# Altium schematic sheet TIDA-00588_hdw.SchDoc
size 431 x 279 mm; Date: Not shown in title block; ApprovedBy: Not shown in title block; CheckedBy: Not shown in title block; Author: Not shown in title block; CompanyName: Not shown in title block; Engineer: Not shown in title block; Organization: Not shown in title block; Address1: Not shown in title block; Address2: Not shown in title block; Address3: Not shown in title block; Address4: Not shown in title block; DocumentNumber: 1; Revision: Use project parameter SCH_Rev; SheetNumber: 3; SheetTotal: 3; PageSetup: Record=PageOptions¦CenterHorizontal=True¦CenterVertical=True¦PrintScale=1.00¦XCorrection=1.00¦YCorrection=1.00¦PrintKind=0¦BorderSize=5000000¦LeftOffset=0¦BottomOffset=0¦Orientation=2¦PaperLength=1000¦PaperWidth=1000¦Scale=100¦PaperSource=15¦PrintQuality=600¦MediaType=1¦DitherType=10¦PaperKind=Letter¦PrintScaleMode=1
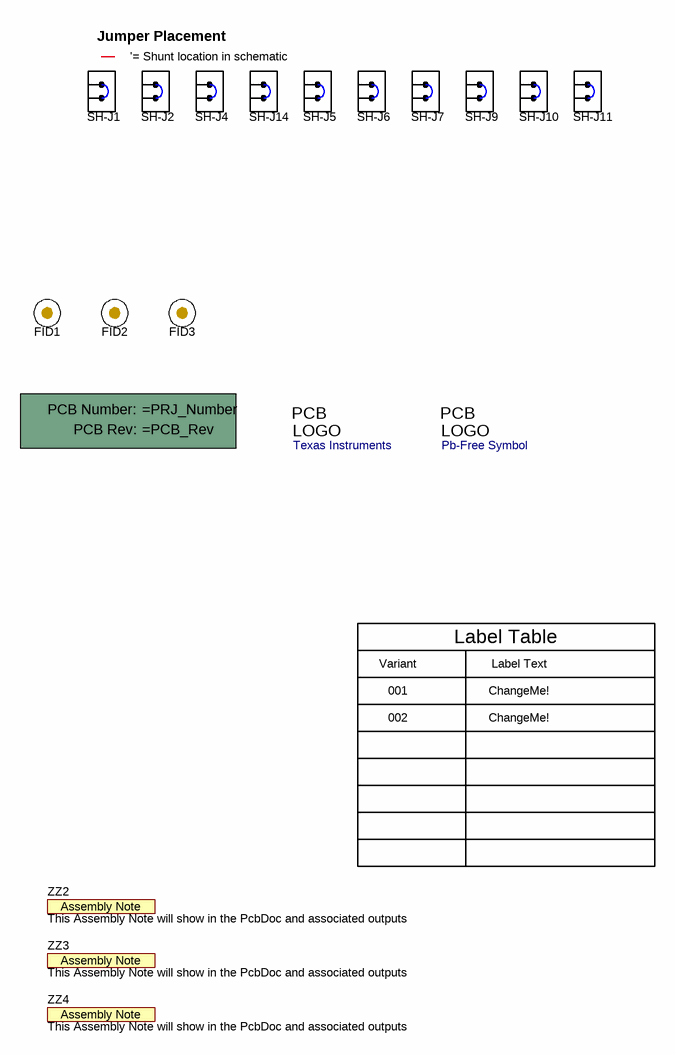
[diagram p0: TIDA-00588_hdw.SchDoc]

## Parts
!PCB1  Printed Circuit Board  (value not drawn)  (mechanical)
FID1  Fiducial  [Fiducial10-20]  (value not drawn)
FID2  Fiducial  [Fiducial10-20]  (value not drawn)
FID3  Fiducial  [Fiducial10-20]  (value not drawn)
Logo1  Texas Instruments  [TI_Stacked_SolderMask_Small]  (no BOM)
Logo2  Pb-Free Symbol  [Pb-Free_Overlay_Small]  (no BOM)
SH-J1  969102-0000-DA  [SNT-100-BK-G]  (value not drawn)
SH-J2  969102-0000-DA  [SNT-100-BK-G]  (value not drawn)
SH-J4  969102-0000-DA  [SNT-100-BK-G]  (value not drawn)
SH-J5  969102-0000-DA  [SNT-100-BK-G]  (value not drawn)
SH-J6  969102-0000-DA  [SNT-100-BK-G]  (value not drawn)
SH-J7  969102-0000-DA  [SNT-100-BK-G]  (value not drawn)
SH-J9  969102-0000-DA  [SNT-100-BK-G]  (value not drawn)
SH-J10  969102-0000-DA  [SNT-100-BK-G]  (value not drawn)
SH-J11  969102-0000-DA  [SNT-100-BK-G]  (value not drawn)
SH-J14  969102-0000-DA  [SNT-100-BK-G]  (value not drawn)
ZZ2  This Assembly Note will show in the PcbDoc and associated outputs  [AssemblyNote]  (no BOM)
ZZ3  This Assembly Note will show in the PcbDoc and associated outputs  [AssemblyNote]  (no BOM)
ZZ4  This Assembly Note will show in the PcbDoc and associated outputs  [AssemblyNote]  (no BOM)

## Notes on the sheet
- Jumper Placement
- '= Shunt location in schematic
- Variant
- Label Table
- Label Text
- 001
- 002
- ChangeMe!

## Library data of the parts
!PCB1 = PCB: Manufacturer: Any; SymbolCreator: a0412235
FID1-FID3 = Fiducial: Fiducial mark.  There is nothing to buy or mount.; SymbolCreator: codlsc
Logo1 = TI_Logo: Texas Instrument Corporate Signature; SymbolCreator: a0412235
Logo2 = Pb-Free: SymbolCreator: a0412235
SH-J1 SH-J2 SH-J4-SH-J7 SH-J9-SH-J11 SH-J14 = 969102-0000-DA: Shunt, 100mil, Gold plated, Black; Manufacturer: 3M; Alternate Manufacturer: Samtec; Value: 1x2; Note: You can "mate" this to a header by matching the designator.  i.e. use SH-J3 for header J3
ZZ2-ZZ4 = AssemblyNote: SymbolCreator: codlsc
